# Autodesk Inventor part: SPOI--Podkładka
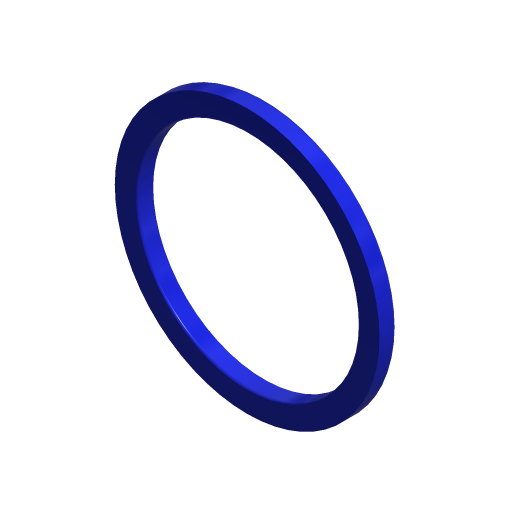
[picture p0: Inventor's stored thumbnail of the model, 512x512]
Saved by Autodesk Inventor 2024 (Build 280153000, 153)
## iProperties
Company: ATC
Shininess: 0.0
Length Units: 11269
Angle Units: 11279
Time Units: 11290
Mass Units: 11283
Length Display Precision: 3
Angle Display Precision: 2
Compacted: True
Created: 2023-03
Part Number: SPOI--Podkładka
Document SubType Name: Modeling
Designer: Andrzej Jaskulski
Material: Kurs-AJ
Density: 1 g/cm^3
Mass: 0.424834 g
Surface Area: 7.40408 cm^2
Volume: 0.424834 cm^3
Appearance: Niebieska — farba ścienna — lśniąca
Checked By: A.J.
Engr Approved By: Andrzej Jaskulski
Mfg Approved By: Andrzej Jaskulski
Authority: A.J.
Density: 0.0
Volumn: 0.0
Area: 0.0
PropertySet Name: Model Information
Control State: 0
Master: False
Checked Out: False
Title: A.J.: Kurs R2024-MEP
Author: Andrzej Jaskulski
Revision Number: 1/24
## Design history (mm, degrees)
node "Extrusion1" dims "d2" = 2, "d3" = 0
node "Fillet1" dims "d4" = 0.25, "d5" = 0.5
node "Bryła1"
node "Korpusy bryłowe"
node "Korpusy powierzchniowe"
sketch "Sketch1"
  geometry: C1 r 12.5 at (36, 61); C2 r 15 at (36, 61)
  constraints: 2 centre point, 1 coincident
  dimensions: "d0" = 25 diameter of C1; "d1" = 30 diameter of C2
